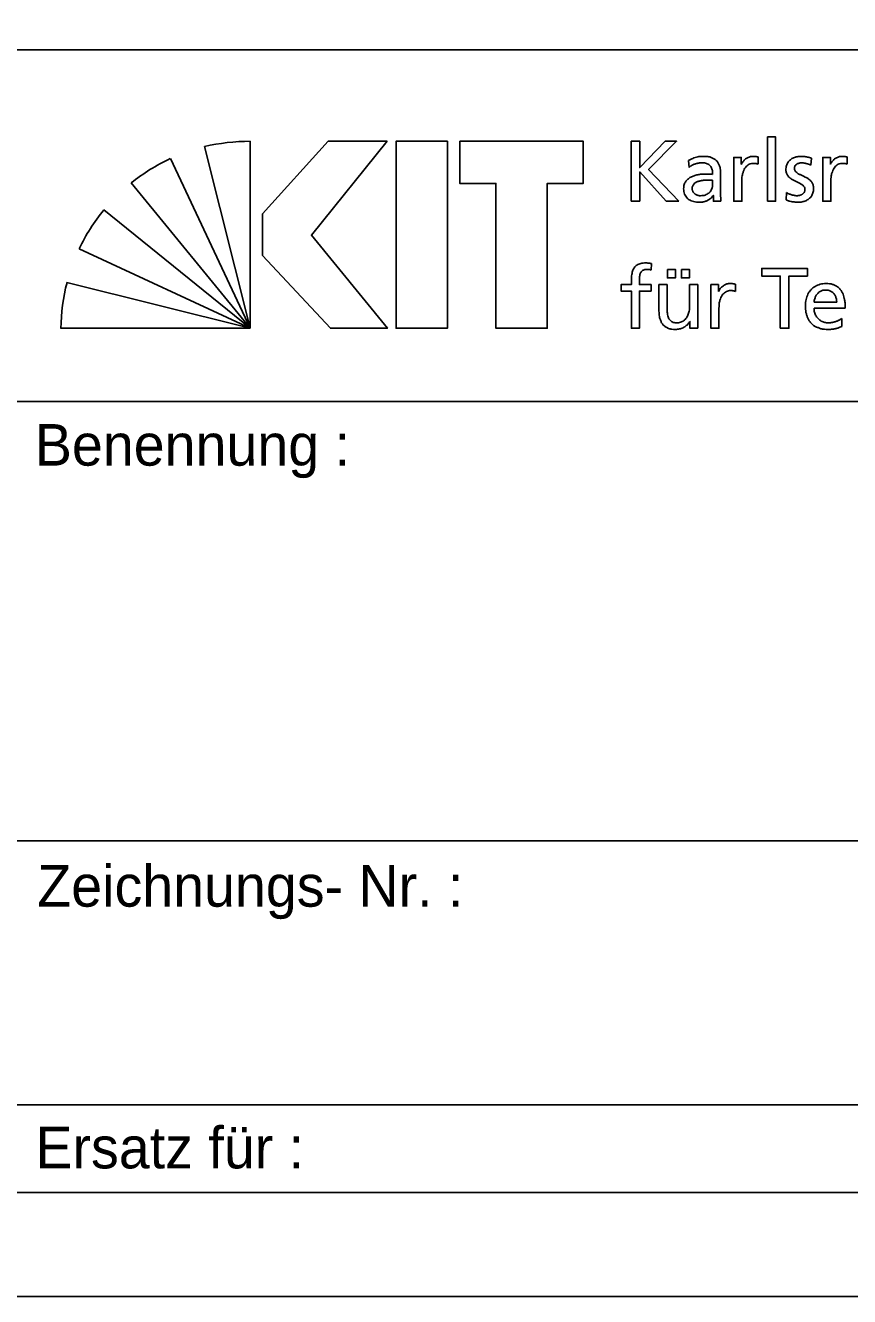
# Model space of a CAD drawing. Extents: x 0 to 297, y 0 to 210.
# Drawn here: x 275.16 to 285.08, y 0 to 15.29 of the extents above; entities that cross this region are included whole.
import ezdxf

# ---------------------------------------------------------------- set-up
doc = ezdxf.new("R2010")
doc.units = 0
doc.layers.add('90_Plankopf', color=7, linetype='Continuous')

msp = doc.modelspace()

# ---------------------------------------------------------------- linework, layer by layer
at = {"layer": '90_Plankopf'}
for p, q in [((251.53, 14.998), (296, 14.998)), ((251.53, 14.998), (296, 14.998)), ((277.319, 13.833), (277.87, 11.647)), ((277.87, 11.647), (277.87, 13.896)), ((282.452, 13.897), (282.452, 13.176)), ((277.87, 11.647), (276.908, 13.688)), ((283.145, 13.665), (283.15, 13.583)), ((283.982, 13.621), (283.982, 13.708)), ((284.614, 13.61), (284.622, 13.694)), ((285.053, 13.621), (285.053, 13.708)), ((283.53, 13.28), (283.53, 13.497)), ((276.436, 13.396), (277.87, 11.647)), ((283.433, 13.427), (283.433, 13.381)), ((282.452, 13.176), (282.556, 13.176)), ((282.876, 13.176), (283.027, 13.176)), ((284.324, 13.28), (284.319, 13.193)), ((277.87, 11.647), (276.108, 13.071)), ((275.81, 12.603), (277.87, 11.647)), ((282.693, 12.348), (282.697, 12.427)), ((277.87, 11.647), (275.664, 12.197)), ((283.707, 12.091), (283.707, 12.178)), ((284.927, 11.96), (284.654, 11.96)), ((284.654, 11.888), (285.03, 11.888)), ((275.591, 11.647), (277.87, 11.647)), ((284.989, 11.668), (284.989, 11.765)), ((275, 10.768), (296, 10.768)), ((275, 5.48), (296, 5.48)), ((275, 2.308), (296, 2.308)), ((296, 1.25), (251.53, 1.25)), ((254.45, 1.25), (296, 1.25)), ((254.45, 1.25), (296, 1.25))]:
    msp.add_line(p, q, dxfattribs=at)
for points in [[(0, 0), (297.25, 0), (297.25, 210.25), (0, 210.25)], [(6.25, 1.25), (296, 1.25), (296, 209), (6.25, 209)], [(279.517, 13.897), (278.809, 13.897), (278.018, 13.025), (278.018, 12.523), (278.834, 11.647), (279.521, 11.647), (278.606, 12.766)], [(280.243, 13.897), (280.243, 11.647), (279.625, 11.647), (279.625, 13.897)], [(280.391, 13.897), (280.391, 13.39), (280.825, 13.39), (280.825, 11.647), (281.443, 11.647), (281.443, 13.39), (281.877, 13.39), (281.877, 13.897)]]:
    msp.add_lwpolyline(points, close=True, dxfattribs=at)
for points in [[(284.095, 13.176), (284.192, 13.176), (284.192, 13.95), (284.095, 13.95), (284.095, 13.176)], [(283.027, 13.176), (282.662, 13.556), (283, 13.897), (282.863, 13.897), (282.556, 13.58), (282.556, 13.897), (282.452, 13.897)], [(283.78, 13.621), (283.778, 13.621), (283.778, 13.703), (283.688, 13.703), (283.688, 13.176), (283.785, 13.176), (283.785, 13.416)], [(284.852, 13.621), (284.85, 13.621), (284.85, 13.703), (284.759, 13.703), (284.759, 13.176), (284.856, 13.176), (284.856, 13.416)], [(282.556, 13.176), (282.556, 13.529), (282.876, 13.176)], [(283.441, 13.245), (283.443, 13.245), (283.443, 13.176), (283.534, 13.176)], [(282.889, 12.356), (282.889, 12.253), (282.986, 12.253), (282.986, 12.356), (282.889, 12.356)], [(283.058, 12.356), (283.058, 12.253), (283.155, 12.253), (283.155, 12.356), (283.058, 12.356)], [(284.248, 11.647), (284.351, 11.647), (284.351, 12.276), (284.575, 12.276), (284.575, 12.367), (284.024, 12.367), (284.024, 12.276), (284.248, 12.276), (284.248, 11.647)], [(282.456, 12.221), (282.456, 12.173), (282.332, 12.173), (282.332, 12.094), (282.456, 12.094), (282.456, 11.647), (282.553, 11.647), (282.553, 12.094), (282.692, 12.094), (282.692, 12.173), (282.553, 12.173), (282.553, 12.23)], [(282.885, 11.9), (282.885, 12.173), (282.788, 12.173), (282.788, 11.86)], [(283.254, 11.647), (283.254, 12.173), (283.157, 12.173), (283.157, 11.929)], [(283.506, 12.091), (283.504, 12.091), (283.504, 12.173), (283.413, 12.173), (283.413, 11.647), (283.51, 11.647), (283.51, 11.886)], [(283.158, 11.73), (283.16, 11.73), (283.16, 11.647), (283.254, 11.647)]]:
    msp.add_lwpolyline(points, dxfattribs=at)
for centre, start, end in [((277.862, 11.514), 89.8053, 103.1895), ((277.915, 11.529), 115.0126, 128.3968), ((277.954, 11.566), 140.7898, 154.174), ((277.973, 11.609), 165.7222, 179.1064)]:
    msp.add_arc(centre, 2.382, start, end, dxfattribs=at)
for points in [[(283.53, 13.497), (283.53, 13.545), (283.523, 13.585), (283.508, 13.617), (283.494, 13.65), (283.471, 13.674), (283.44, 13.69), (283.409, 13.707), (283.368, 13.715), (283.318, 13.715), (283.285, 13.715), (283.253, 13.71), (283.224, 13.701), (283.195, 13.692), (283.169, 13.68), (283.145, 13.665)], [(283.15, 13.583), (283.163, 13.594), (283.178, 13.604), (283.195, 13.611), (283.211, 13.62), (283.229, 13.626), (283.247, 13.63), (283.266, 13.634), (283.284, 13.637), (283.303, 13.637), (283.335, 13.637), (283.36, 13.631), (283.379, 13.621), (283.399, 13.611), (283.412, 13.596), (283.42, 13.575), (283.429, 13.555), (283.433, 13.53), (283.433, 13.499)], [(283.982, 13.708), (283.975, 13.709), (283.968, 13.71), (283.962, 13.712), (283.956, 13.713), (283.949, 13.713), (283.942, 13.714), (283.935, 13.715), (283.927, 13.715), (283.918, 13.715), (283.899, 13.715), (283.881, 13.711), (283.863, 13.703), (283.845, 13.695), (283.829, 13.684), (283.815, 13.67), (283.801, 13.656), (283.789, 13.639), (283.78, 13.621)], [(283.785, 13.416), (283.785, 13.46), (283.791, 13.498), (283.802, 13.53), (283.814, 13.562), (283.831, 13.587), (283.852, 13.604), (283.874, 13.621), (283.899, 13.63), (283.928, 13.63), (283.936, 13.631), (283.945, 13.63), (283.954, 13.629), (283.964, 13.627), (283.973, 13.625), (283.982, 13.621)], [(284.622, 13.694), (284.604, 13.7), (284.584, 13.705), (284.565, 13.709), (284.545, 13.713), (284.524, 13.715), (284.502, 13.715), (284.476, 13.715), (284.451, 13.712), (284.429, 13.705), (284.406, 13.698), (284.387, 13.688), (284.37, 13.675), (284.353, 13.662), (284.34, 13.645), (284.33, 13.625), (284.321, 13.604), (284.316, 13.58), (284.316, 13.553), (284.316, 13.532), (284.321, 13.514), (284.329, 13.498), (284.337, 13.483), (284.348, 13.47), (284.361, 13.459), (284.375, 13.447), (284.39, 13.437), (284.406, 13.429), (284.422, 13.42), (284.438, 13.412), (284.454, 13.404), (284.471, 13.397), (284.485, 13.389), (284.499, 13.38), (284.512, 13.373), (284.523, 13.363), (284.532, 13.353), (284.54, 13.343), (284.544, 13.331), (284.544, 13.318), (284.544, 13.304), (284.541, 13.292), (284.535, 13.282), (284.529, 13.272), (284.521, 13.265), (284.511, 13.259), (284.501, 13.253), (284.491, 13.249), (284.479, 13.246), (284.468, 13.244), (284.456, 13.242), (284.445, 13.242), (284.435, 13.242), (284.424, 13.244), (284.41, 13.247), (284.396, 13.249), (284.381, 13.253), (284.366, 13.259), (284.351, 13.265), (284.337, 13.271), (284.324, 13.28)], [(284.319, 13.193), (284.342, 13.181), (284.365, 13.174), (284.389, 13.17), (284.414, 13.166), (284.439, 13.164), (284.464, 13.164), (284.487, 13.164), (284.51, 13.167), (284.532, 13.174), (284.554, 13.18), (284.573, 13.191), (284.591, 13.204), (284.608, 13.217), (284.622, 13.234), (284.632, 13.255), (284.642, 13.276), (284.647, 13.3), (284.647, 13.328), (284.647, 13.352), (284.643, 13.372), (284.635, 13.389), (284.626, 13.406), (284.616, 13.42), (284.602, 13.431), (284.589, 13.443), (284.574, 13.453), (284.557, 13.461), (284.541, 13.469), (284.525, 13.477), (284.509, 13.484), (284.493, 13.491), (284.478, 13.499), (284.464, 13.507), (284.451, 13.515), (284.44, 13.524), (284.432, 13.534), (284.424, 13.545), (284.419, 13.557), (284.419, 13.573), (284.419, 13.587), (284.424, 13.599), (284.432, 13.609), (284.441, 13.618), (284.452, 13.625), (284.466, 13.63), (284.48, 13.634), (284.495, 13.637), (284.512, 13.637), (284.518, 13.637), (284.526, 13.636), (284.535, 13.634), (284.544, 13.633), (284.553, 13.631), (284.564, 13.628), (284.574, 13.626), (284.583, 13.623), (284.592, 13.62), (284.601, 13.616), (284.609, 13.613), (284.614, 13.61)], [(285.053, 13.708), (285.046, 13.709), (285.04, 13.71), (285.034, 13.712), (285.027, 13.713), (285.021, 13.713), (285.014, 13.714), (285.007, 13.715), (284.998, 13.715), (284.989, 13.715), (284.97, 13.715), (284.952, 13.711), (284.934, 13.703), (284.917, 13.695), (284.901, 13.684), (284.886, 13.67), (284.872, 13.656), (284.86, 13.639), (284.852, 13.621)], [(284.856, 13.416), (284.856, 13.46), (284.862, 13.498), (284.874, 13.53), (284.886, 13.562), (284.902, 13.587), (284.923, 13.604), (284.945, 13.621), (284.97, 13.63), (284.999, 13.63), (285.008, 13.631), (285.016, 13.63), (285.026, 13.629), (285.035, 13.627), (285.044, 13.625), (285.053, 13.621)], [(283.433, 13.499), (283.42, 13.5), (283.408, 13.501), (283.397, 13.501), (283.386, 13.501), (283.376, 13.501), (283.365, 13.501), (283.354, 13.501), (283.342, 13.501), (283.329, 13.501), (283.309, 13.501), (283.288, 13.5), (283.266, 13.496), (283.243, 13.492), (283.221, 13.487), (283.2, 13.478), (283.179, 13.47), (283.16, 13.46), (283.142, 13.446), (283.125, 13.433), (283.111, 13.416), (283.101, 13.397), (283.09, 13.377), (283.085, 13.354), (283.085, 13.328), (283.085, 13.29), (283.094, 13.259), (283.11, 13.235), (283.126, 13.211), (283.149, 13.193), (283.177, 13.181), (283.206, 13.17), (283.24, 13.164), (283.278, 13.164), (283.3, 13.164), (283.32, 13.167), (283.338, 13.172), (283.355, 13.177), (283.371, 13.184), (283.384, 13.192), (283.398, 13.2), (283.409, 13.209), (283.418, 13.218), (283.428, 13.228), (283.435, 13.236), (283.441, 13.245)], [(283.433, 13.381), (283.433, 13.354), (283.427, 13.331), (283.416, 13.31), (283.405, 13.289), (283.388, 13.273), (283.367, 13.261), (283.345, 13.249), (283.318, 13.243), (283.286, 13.242), (283.275, 13.242), (283.264, 13.244), (283.252, 13.248), (283.241, 13.252), (283.23, 13.257), (283.22, 13.264), (283.211, 13.272), (283.203, 13.281), (283.197, 13.291), (283.191, 13.302), (283.188, 13.314), (283.188, 13.328), (283.188, 13.347), (283.193, 13.362), (283.202, 13.374), (283.211, 13.387), (283.223, 13.396), (283.237, 13.404), (283.252, 13.411), (283.267, 13.417), (283.284, 13.42), (283.3, 13.424), (283.316, 13.426), (283.332, 13.428), (283.347, 13.429), (283.36, 13.429), (283.371, 13.429), (283.381, 13.429), (283.391, 13.429), (283.402, 13.428), (283.412, 13.428), (283.422, 13.427), (283.433, 13.427)], [(283.534, 13.176), (283.533, 13.181), (283.532, 13.188), (283.532, 13.197), (283.531, 13.205), (283.531, 13.216), (283.53, 13.23), (283.53, 13.243), (283.53, 13.26), (283.53, 13.28)], [(282.697, 12.427), (282.688, 12.428), (282.678, 12.43), (282.667, 12.431), (282.656, 12.432), (282.645, 12.433), (282.632, 12.433), (282.597, 12.433), (282.568, 12.428), (282.544, 12.418), (282.521, 12.408), (282.503, 12.394), (282.491, 12.375), (282.478, 12.356), (282.469, 12.334), (282.464, 12.308), (282.458, 12.282), (282.456, 12.253), (282.456, 12.221)], [(282.553, 12.23), (282.553, 12.247), (282.554, 12.264), (282.556, 12.279), (282.558, 12.294), (282.562, 12.307), (282.569, 12.319), (282.575, 12.33), (282.585, 12.339), (282.597, 12.345), (282.61, 12.351), (282.626, 12.354), (282.647, 12.354), (282.655, 12.354), (282.664, 12.354), (282.672, 12.353), (282.68, 12.352), (282.688, 12.35), (282.693, 12.348)], [(283.707, 12.178), (283.7, 12.179), (283.693, 12.181), (283.688, 12.182), (283.681, 12.183), (283.675, 12.184), (283.667, 12.184), (283.661, 12.185), (283.652, 12.185), (283.643, 12.185), (283.624, 12.185), (283.606, 12.181), (283.588, 12.173), (283.571, 12.165), (283.555, 12.154), (283.54, 12.14), (283.526, 12.126), (283.514, 12.11), (283.506, 12.091)], [(283.51, 11.886), (283.51, 11.93), (283.516, 11.968), (283.528, 12), (283.539, 12.032), (283.556, 12.057), (283.577, 12.074), (283.599, 12.092), (283.624, 12.1), (283.653, 12.1), (283.662, 12.101), (283.67, 12.1), (283.68, 12.099), (283.689, 12.097), (283.698, 12.095), (283.707, 12.091)], [(285.03, 11.888), (285.03, 11.931), (285.026, 11.97), (285.018, 12.006), (285.01, 12.042), (284.997, 12.073), (284.979, 12.1), (284.961, 12.127), (284.938, 12.148), (284.908, 12.162), (284.878, 12.177), (284.841, 12.185), (284.797, 12.185), (284.76, 12.185), (284.726, 12.178), (284.696, 12.166), (284.666, 12.152), (284.64, 12.134), (284.618, 12.111), (284.597, 12.087), (284.58, 12.059), (284.569, 12.026), (284.557, 11.994), (284.551, 11.958), (284.551, 11.919), (284.551, 11.876), (284.556, 11.837), (284.567, 11.802), (284.578, 11.767), (284.595, 11.737), (284.617, 11.712), (284.639, 11.687), (284.668, 11.668), (284.702, 11.655), (284.736, 11.641), (284.777, 11.634), (284.823, 11.634), (284.852, 11.634), (284.876, 11.636), (284.897, 11.64), (284.917, 11.644), (284.934, 11.648), (284.949, 11.653), (284.964, 11.659), (284.977, 11.664), (284.989, 11.668)], [(284.654, 11.96), (284.656, 11.977), (284.66, 11.995), (284.666, 12.012), (284.672, 12.029), (284.681, 12.045), (284.692, 12.059), (284.703, 12.073), (284.717, 12.085), (284.734, 12.093), (284.751, 12.102), (284.772, 12.107), (284.795, 12.107), (284.816, 12.107), (284.835, 12.103), (284.851, 12.095), (284.867, 12.088), (284.881, 12.077), (284.892, 12.064), (284.903, 12.05), (284.912, 12.035), (284.918, 12.017), (284.924, 11.999), (284.927, 11.981), (284.927, 11.96)], [(283.157, 11.929), (283.157, 11.897), (283.154, 11.868), (283.147, 11.841), (283.141, 11.815), (283.131, 11.792), (283.118, 11.773), (283.105, 11.754), (283.088, 11.739), (283.068, 11.728), (283.048, 11.718), (283.024, 11.713), (282.997, 11.713), (282.969, 11.714), (282.947, 11.722), (282.93, 11.736), (282.914, 11.75), (282.902, 11.771), (282.895, 11.798), (282.889, 11.825), (282.885, 11.859), (282.885, 11.9)], [(282.788, 11.86), (282.788, 11.813), (282.795, 11.772), (282.809, 11.739), (282.823, 11.705), (282.845, 11.679), (282.874, 11.661), (282.903, 11.644), (282.94, 11.634), (282.986, 11.634), (283.01, 11.634), (283.034, 11.638), (283.056, 11.646), (283.079, 11.653), (283.099, 11.665), (283.117, 11.679), (283.134, 11.693), (283.148, 11.71), (283.158, 11.73)], [(284.989, 11.765), (284.983, 11.76), (284.975, 11.755), (284.963, 11.749), (284.952, 11.743), (284.939, 11.737), (284.924, 11.732), (284.909, 11.726), (284.893, 11.722), (284.876, 11.718), (284.86, 11.715), (284.844, 11.713), (284.827, 11.713), (284.804, 11.713), (284.782, 11.717), (284.762, 11.725), (284.741, 11.734), (284.722, 11.746), (284.706, 11.761), (284.69, 11.777), (284.677, 11.795), (284.668, 11.817), (284.659, 11.838), (284.654, 11.862), (284.654, 11.888)]]:
    msp.add_open_spline(points, degree=3, dxfattribs=at)

# ---------------------------------------------------------------- texts
for s, p in [('Benennung :', (275.278, 9.995)), ('Zeichnungs- Nr. :', (275.307, 4.69)), ('Ersatz für :', (275.285, 1.542))]:
    msp.add_text(s, height=0.5, dxfattribs=at).set_placement(p)

doc.saveas('drawing.dxf')
